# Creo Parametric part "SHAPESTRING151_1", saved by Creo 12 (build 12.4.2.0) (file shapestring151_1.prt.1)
Units: Custom; MM, KILOGRAM, SECS

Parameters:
  PTC_WM_ITERATION = "0"
  PTC_WM_VERSION = "-.0"
  PTC_WM_LIFECYCLE_STATE = "In Work"
  PTC_WM_LIFECYCLE = "MO_CADDocument"
  PTC_WM_CREATED_BY = "Maximilian Roepper (Z0017RMS: MO)"
  PTC_WM_CREATED_ON = "18-Sep-26 11:36:42 AM"
  PTC_WM_MODIFIED_BY = "Maximilian Roepper (Z0017RMS: MO)"
  PTC_WM_MODIFIED_ON = "18-Sep-26 11:36:46 AM"
  PDMLINKNUMBER = "PDM000071455151"
  PTC_WM_NAME = "shapestring151_1.prt"
  PTC_WM_NUMBER = "PDM000071455151"

Other parameters: WEIGHT, WEIGHT_FACTOR, WEIGHT_ADD, _MASS_TEMP, _DIFF_TEMP, MC_ERRORS, SUPPLIER

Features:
  1. coordinate system
  2. datum plane "PRT_YZ"
  3. datum plane "PRT_XY"
  4. datum plane "PRT_XZ"
  5. coordinate system
  6. datum axis
  7. datum axis
  8. datum axis
  9. coordinate system
  10. imported feature
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
Other named items: PRT, SIEMENS_MO, DRW_VIEW_ORG, PRT_X, PRT_Y, PRT_Z, CS0, ROUGH_GROB

Layers: 00_STD_CSYS-KSYS, 01_STD_PLANES-EBENEN, 02_STD_AXES-ACHSEN, 03_STD_CSYS-KSYS, 24_IMPORT_FEAT-IMPORT_KE, INTFCLR

Surfaces: 1 plane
